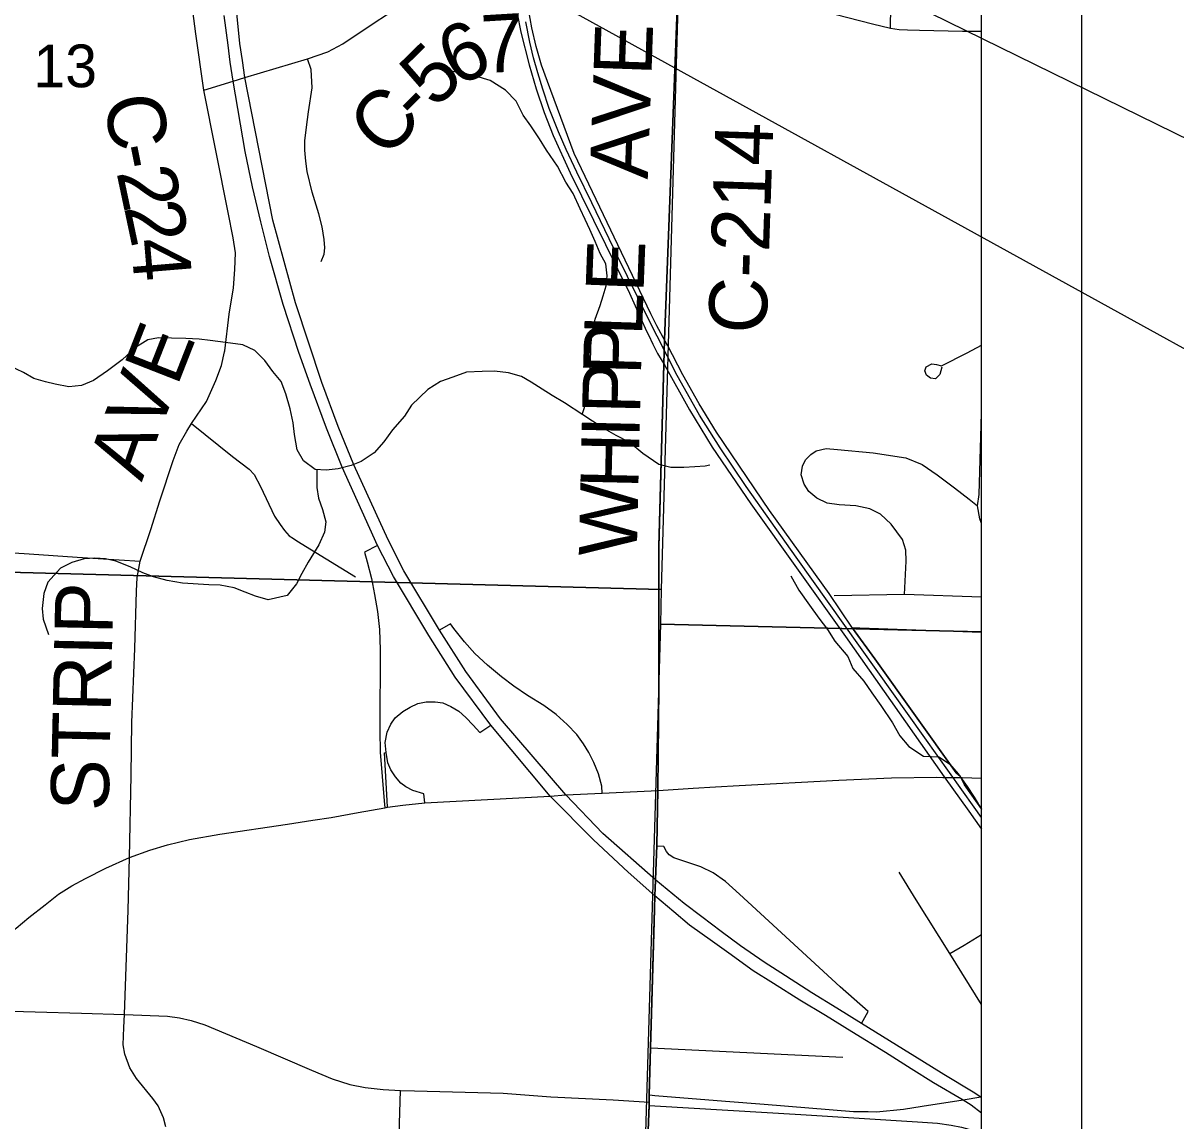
# Model space of a CAD drawing. Extents: x 0 to 34, y 0 to 22.
# Drawn here: x 8.698 to 9.827, y 17.297 to 18.372 of the extents above; entities that cross this region are included whole.
import ezdxf

# ---------------------------------------------------------------- set-up
doc = ezdxf.new("R2010")
doc.units = 0
for name, color, linetype in [('GM_X_City_Street', 7, 'Continuous'), ('GM_X_Corporation', 7, 'Continuous'), ('GM_X_County_Road', 7, 'Continuous'), ('GM_X_County_Road_Text', 7, 'Continuous'), ('GM_X_Interchange_Ramps', 7, 'Continuous'), ('GM_X_Interstate_Route', 7, 'Continuous'), ('GM_X_Minor_River', 7, 'Continuous'), ('GM_X_Rail_Line', 7, 'Continuous'), ('GM_X_Section_Text', 7, 'Continuous'), ('GM_X_Township_Road', 7, 'Continuous'), ('SH_Data', 7, 'Continuous'), ('SH_Text', 7, 'Continuous')]:
    doc.layers.add(name, color=color, linetype=linetype)

msp = doc.modelspace()

# ---------------------------------------------------------------- linework, layer by layer
at = {"layer": 'GM_X_City_Street'}
msp.add_line((9.6367, 17.9784), (9.637, 17.9905), dxfattribs=at)
for points in [[(9.5477, 18.3676), (9.5505, 18.5393), (9.5497, 18.5492), (9.5474, 18.5571), (9.5429, 18.5632)], [(9.598, 18.0352), (9.5961, 18.0281), (9.592, 18.0238), (9.5869, 18.0244), (9.5831, 18.0274), (9.5814, 18.0317), (9.5826, 18.0356), (9.5882, 18.0385), (9.593, 18.0378), (9.5979, 18.0366), (9.623, 18.0493), (9.637, 18.0569)]]:
    msp.add_lwpolyline(points, dxfattribs=at)
at = {"layer": 'GM_X_Corporation'}
for points in [[(7.1023, 20.9204), (2.837, 20.9204), (2.837, 14.1204), (9.637, 14.1204), (9.637, 20.9204), (9.4036, 20.9204), (9.4022, 20.8667), (9.2273, 20.8723), (9.1354, 20.8749), (9.124, 20.8753), (8.9858, 20.878), (8.9676, 20.8785), (8.8663, 20.881), (8.6259, 20.8892), (8.5535, 20.8914), (8.5421, 20.8915), (8.4667, 20.8934), (8.0602, 20.9055), (7.9522, 20.9084), (7.1104, 20.9188)], [(8.3333, 18.8624), (9.3514, 18.838), (9.3511, 18.8009), (9.3232, 17.8175), (8.3013, 17.8445)], [(9.637, 17.7759), (9.637, 18.7908), (9.3511, 18.8009), (9.3232, 17.8175), (9.3224, 17.7834)], [(8.3013, 17.8445), (9.3232, 17.8175), (9.3224, 17.7834), (9.2937, 16.8089), (8.2669, 16.8377)], [(9.637, 16.7685), (9.637, 17.7759), (9.3224, 17.7834), (9.2937, 16.8089), (9.2941, 16.7789)], [(9.637, 17.6026), (9.637, 17.7754), (9.5178, 17.7796), (9.5107, 17.7797), (9.5323, 17.7495), (9.612, 17.6378), (9.6161, 17.6346), (9.6203, 17.6261)]]:
    msp.add_lwpolyline(points, close=True, dxfattribs=at)
for points in [[(9.637, 14.7553), (9.637, 20.8621)], [(9.3401, 18.421), (9.3264, 18.0621), (9.3258, 18.0384), (9.321, 17.8596), (9.3207, 17.721), (9.32, 17.6211), (9.3188, 17.5666), (9.3177, 17.5332), (9.3173, 17.5248), (9.3168, 17.5178), (9.3167, 17.5046), (9.3128, 17.3688), (9.3114, 17.3225), (9.3115, 17.3158), (9.3114, 17.3124), (9.3077, 17.2197)], [(9.3077, 17.2197), (9.3114, 17.3124), (9.3115, 17.3158), (9.3114, 17.3225), (9.3128, 17.3688), (9.3167, 17.5046), (9.3168, 17.5178), (9.3173, 17.5248), (9.3177, 17.5332), (9.3188, 17.5666), (9.32, 17.6211), (9.3207, 17.721), (9.321, 17.8596), (9.3258, 18.0384), (9.3264, 18.0621), (9.3401, 18.421)], [(9.182, 18.3819), (9.1856, 18.3635), (9.1939, 18.3316), (9.2007, 18.3081), (9.2086, 18.285), (9.2174, 18.2622), (9.2341, 18.2258), (9.2452, 18.2031), (9.292, 18.1079), (9.3088, 18.0707), (9.3106, 18.0671), (9.3151, 18.0579), (9.3197, 18.0487), (9.3266, 18.0371), (9.3508, 17.9934), (9.373, 17.957), (9.4109, 17.9013), (9.5036, 17.7713), (9.6005, 17.634), (9.6246, 17.6002), (9.637, 17.5826), (9.637, 17.6026), (9.6203, 17.6261), (9.6161, 17.6346), (9.612, 17.6378), (9.5323, 17.7495), (9.5107, 17.7797), (9.4877, 17.8135), (9.4292, 17.8948), (9.3772, 17.9716), (9.3604, 17.9995), (9.3444, 18.0279), (9.3292, 18.0568), (9.3272, 18.0607), (9.3189, 18.0757), (9.313, 18.0876), (9.2378, 18.2446), (9.2117, 18.3152), (9.2058, 18.3313), (9.2007, 18.3494), (9.1965, 18.3677), (9.1931, 18.3862)]]:
    msp.add_lwpolyline(points, dxfattribs=at)
at = {"layer": 'GM_X_County_Road'}
for p, q in [((9.3202, 17.6205), (9.3206, 17.671)), ((9.593, 17.6335), (9.599, 17.6334)), ((9.599, 17.6334), (9.609, 17.6334)), ((9.6179, 17.6332), (9.637, 17.6326))]:
    msp.add_line(p, q, dxfattribs=at)
for points in [[(8.8752, 18.3068), (8.8672, 18.3619), (8.8625, 18.3998), (8.8597, 18.4111), (8.8534, 18.4289), (8.8412, 18.4603), (8.8205, 18.5154), (8.8175, 18.533), (8.8161, 18.548), (8.817, 18.5673), (8.8185, 18.588), (8.8196, 18.6158), (8.82, 18.6436), (8.8209, 18.7158)], [(9.3268, 18.0667), (9.3403, 18.4205), (9.3424, 18.5015), (9.3424, 18.5335), (9.3404, 18.5527), (9.336, 18.5745), (9.3314, 18.5903), (9.3271, 18.6029), (9.319, 18.6238)], [(8.8752, 18.3068), (8.9039, 18.3157), (8.9154, 18.3192), (8.9766, 18.3375), (8.9966, 18.3444), (9.0112, 18.3522), (9.0421, 18.3726), (9.0662, 18.3883), (9.0904, 18.4041), (9.1049, 18.4132), (9.1159, 18.4183), (9.1291, 18.4224), (9.1482, 18.425), (9.1708, 18.4247)], [(9.3403, 18.4205), (9.4334, 18.3962), (9.4817, 18.384), (9.5302, 18.3718), (9.5477, 18.3676), (9.5562, 18.3663), (9.5646, 18.3658), (9.5762, 18.3656), (9.6184, 18.3646), (9.637, 18.3645)], [(8.8957, 18.0514), (8.8999, 18.0871), (8.9042, 18.113), (8.9054, 18.1309), (8.906, 18.1475), (8.9039, 18.1619), (8.8988, 18.1867), (8.8752, 18.3068)], [(9.3262, 18.0461), (9.3266, 18.0616), (9.3268, 18.0667)], [(8.8126, 17.8453), (8.8233, 17.8761), (8.8321, 17.9045), (8.845, 17.944), (8.8511, 17.9597), (8.8585, 17.9726), (8.863, 17.98), (8.8776, 18.0017), (8.8868, 18.0223), (8.8925, 18.0368), (8.8955, 18.0503), (8.8957, 18.0514)], [(9.3212, 17.8539), (9.3212, 17.859), (9.326, 18.0379), (9.3262, 18.0461)], [(8.8023, 17.5549), (8.8038, 17.6353), (8.8047, 17.6873), (8.8075, 17.7597), (8.809, 17.8159), (8.8098, 17.8291), (8.8126, 17.8453)], [(9.3206, 17.671), (9.3209, 17.7204), (9.3212, 17.8539)], [(9.3994, 17.6253), (9.4973, 17.6307), (9.5487, 17.6329), (9.593, 17.6335)], [(9.609, 17.6334), (9.613, 17.6334), (9.6179, 17.6332)], [(9.0552, 17.6041), (9.0702, 17.6062), (9.0916, 17.6085), (9.2144, 17.6151), (9.2298, 17.6162), (9.2655, 17.618), (9.3202, 17.6205)], [(9.3162, 17.4807), (9.3169, 17.504), (9.317, 17.5172), (9.3175, 17.5243), (9.3179, 17.5327), (9.319, 17.5661), (9.3202, 17.6205)], [(9.3202, 17.6205), (9.3544, 17.6229), (9.3764, 17.6241), (9.3994, 17.6253)], [(8.982, 17.5913), (8.9999, 17.594), (9.0264, 17.5991), (9.0524, 17.6037), (9.0552, 17.6041)], [(8.8023, 17.5549), (8.8221, 17.5619), (8.8396, 17.5672), (8.861, 17.5725), (8.8908, 17.5777), (8.9572, 17.5875), (8.982, 17.5913)], [(8.6251, 17.4058), (8.6447, 17.4338), (8.66, 17.4535), (8.676, 17.4708), (8.6912, 17.4855), (8.7037, 17.4961), (8.7196, 17.5085), (8.7328, 17.5188), (8.7459, 17.5271), (8.7592, 17.5343), (8.7791, 17.5445), (8.8023, 17.5549)], [(8.8379, 17.2909), (8.8357, 17.2997), (8.8304, 17.3114), (8.825, 17.3189), (8.8092, 17.3384), (8.8026, 17.3489), (8.7976, 17.3622), (8.7961, 17.3712), (8.7966, 17.3883), (8.7974, 17.4011), (8.8011, 17.5032), (8.8023, 17.5549)], [(9.3084, 17.2321), (9.3116, 17.3118), (9.3117, 17.3152), (9.3116, 17.322), (9.313, 17.3683), (9.3162, 17.4807)], [(8.6251, 17.4058), (8.6641, 17.405), (8.7554, 17.4022), (8.7974, 17.4011), (8.8395, 17.3993), (8.8513, 17.3978), (8.8628, 17.3953), (8.8761, 17.391), (8.9267, 17.3697), (8.9807, 17.3464), (9.0008, 17.3379), (9.0183, 17.3326), (9.0333, 17.3294), (9.0509, 17.3276), (9.0678, 17.3266), (9.0816, 17.3261), (9.1682, 17.324), (9.215, 17.3205), (9.2762, 17.3173), (9.3117, 17.3152)]]:
    msp.add_lwpolyline(points, dxfattribs=at)
at = {"layer": 'GM_X_Interchange_Ramps'}
msp.add_line((9.4239, 17.3128), (9.3862, 17.3159), dxfattribs=at)
for points in [[(9.0453, 17.8606), (9.0324, 17.854), (9.0351, 17.8447), (9.0393, 17.8283), (9.0423, 17.8127), (9.0451, 17.7959), (9.0471, 17.7784), (9.0479, 17.7585), (9.0475, 17.682), (9.0475, 17.6789)], [(9.2655, 17.618), (9.2649, 17.6249), (9.2619, 17.637), (9.2571, 17.6479), (9.2524, 17.6576), (9.2469, 17.6663), (9.2404, 17.6754), (9.2312, 17.6852), (9.2202, 17.6951), (9.2081, 17.7037), (9.1921, 17.7136), (9.1788, 17.7228), (9.1666, 17.732), (9.1529, 17.7432), (9.1407, 17.7548), (9.1306, 17.7661), (9.1199, 17.7792), (9.1167, 17.7838), (9.106, 17.7777)], [(9.0916, 17.6085), (9.0905, 17.6172), (9.0798, 17.6204), (9.0729, 17.624), (9.068, 17.6278), (9.0629, 17.6338), (9.0582, 17.6407), (9.0555, 17.6477), (9.0538, 17.6576), (9.0529, 17.6677), (9.0547, 17.6777), (9.0584, 17.6856), (9.0625, 17.6916), (9.0701, 17.6979), (9.0774, 17.7021), (9.0848, 17.7057), (9.093, 17.7073), (9.1016, 17.7074), (9.1092, 17.7063), (9.1171, 17.7029), (9.1248, 17.6981), (9.1319, 17.6922), (9.139, 17.6846), (9.1456, 17.6772), (9.1564, 17.6845)], [(9.0475, 17.6789), (9.0478, 17.6582), (9.0517, 17.6104), (9.0524, 17.6037)], [(9.0552, 17.6041), (9.0546, 17.6107), (9.0521, 17.6575), (9.0538, 17.6576)], [(9.5195, 17.3921), (9.526, 17.4039), (9.4986, 17.4282), (9.3998, 17.5189), (9.3861, 17.5313), (9.374, 17.5399), (9.362, 17.5456), (9.3484, 17.5503), (9.3355, 17.5546), (9.331, 17.5574), (9.3284, 17.5607), (9.3259, 17.5655), (9.319, 17.5661)], [(9.3862, 17.3159), (9.3168, 17.3215), (9.3116, 17.322)], [(9.637, 17.3202), (9.6364, 17.32), (9.6189, 17.3172), (9.5789, 17.3109), (9.5606, 17.3081), (9.534, 17.3055), (9.5259, 17.3056)], [(9.3116, 17.3118), (9.317, 17.3117), (9.4601, 17.303)], [(9.5259, 17.3056), (9.5117, 17.3057), (9.4239, 17.3128)], [(9.4601, 17.303), (9.5742, 17.296), (9.5938, 17.2947), (9.6071, 17.2927), (9.6174, 17.2907), (9.628, 17.2876), (9.637, 17.2843)]]:
    msp.add_lwpolyline(points, dxfattribs=at)
at = {"layer": 'GM_X_Interstate_Route'}
for points in [[(9.106, 17.7777), (9.0712, 17.8356), (9.0558, 17.866), (9.022, 17.9397), (9.0067, 17.9772), (8.9908, 18.0203), (8.9648, 18.0983), (8.9426, 18.1794), (8.9154, 18.3192), (8.913, 18.3358), (8.9105, 18.3526), (8.9001, 18.4549), (8.894, 18.5339), (8.8855, 18.6428), (8.8804, 18.7046), (8.8705, 18.8229), (8.8664, 18.8766)], [(9.1564, 17.6845), (9.1213, 17.7317), (9.0956, 17.7723), (9.0608, 17.8302), (9.0453, 17.8606), (9.0105, 17.9373), (8.9952, 17.9756), (8.9792, 18.0187), (8.9681, 18.0498), (8.9528, 18.0967), (8.9395, 18.1437), (8.931, 18.1777), (8.9228, 18.212), (8.9156, 18.2467), (8.9039, 18.3157), (8.9009, 18.334), (8.8989, 18.3509), (8.895, 18.3799)], [(9.2298, 17.6162), (9.1656, 17.6907), (9.1317, 17.7371), (9.106, 17.7777)], [(9.637, 17.3044), (9.6267, 17.3121), (9.6189, 17.3172), (9.5899, 17.3342), (9.5682, 17.3479), (9.543, 17.3638), (9.5098, 17.3842), (9.4841, 17.4002), (9.4591, 17.4152), (9.4331, 17.4314), (9.4132, 17.4439), (9.3895, 17.461), (9.3734, 17.4727), (9.351, 17.4887), (9.3354, 17.5018), (9.317, 17.5172), (9.2908, 17.5404), (9.2569, 17.5723), (9.2144, 17.6151), (9.1564, 17.6845)], [(9.5195, 17.3921), (9.4953, 17.4071), (9.4709, 17.4224), (9.4448, 17.4388), (9.4241, 17.4523), (9.4007, 17.4684), (9.3818, 17.4824), (9.363, 17.4966), (9.3458, 17.5097), (9.3179, 17.5327), (9.2661, 17.5785), (9.2298, 17.6162)], [(9.637, 17.3196), (9.6364, 17.32), (9.6289, 17.3249), (9.5999, 17.3423), (9.5784, 17.3558), (9.5537, 17.3709), (9.5195, 17.3921)]]:
    msp.add_lwpolyline(points, dxfattribs=at)
at = {"layer": 'GM_X_Minor_River'}
for points in [[(9.2456, 17.989), (9.2506, 18.0038), (9.2519, 18.0164), (9.2529, 18.0266), (9.2539, 18.0377), (9.2544, 18.0563), (9.2554, 18.0685), (9.2586, 18.0822), (9.2634, 18.0956), (9.2663, 18.1051), (9.2692, 18.115), (9.2702, 18.1249), (9.2689, 18.1367), (9.2635, 18.1468), (9.2584, 18.1586), (9.2533, 18.1703), (9.2486, 18.1801), (9.2439, 18.1903), (9.2369, 18.2054), (9.2299, 18.2167), (9.2217, 18.2321), (9.2109, 18.2479), (9.2039, 18.2589), (9.1954, 18.2717), (9.188, 18.2822), (9.181, 18.2958), (9.1706, 18.3066), (9.1557, 18.3163), (9.1416, 18.3203), (9.1317, 18.3221), (9.1207, 18.3246), (9.1093, 18.3271), (9.0994, 18.3288)], [(9.3707, 17.9392), (9.3661, 17.9382), (9.3562, 17.9377), (9.3452, 17.9371), (9.3327, 17.9369), (9.3209, 17.9398), (9.3052, 17.9506), (9.2918, 17.9618), (9.2792, 17.9685), (9.2654, 17.9763), (9.2463, 17.9885), (9.2286, 18.0005), (9.2164, 18.0075), (9.2065, 18.0138), (9.1957, 18.0205), (9.1862, 18.0261), (9.1736, 18.0297), (9.1599, 18.0314), (9.1478, 18.0312), (9.1323, 18.0303), (9.119, 18.0255), (9.107, 18.0212), (9.0946, 18.0134), (9.0784, 17.998), (9.0718, 17.9872), (9.0598, 17.9738), (9.0516, 17.9623), (9.0419, 17.9515), (9.0291, 17.9429), (9.0193, 17.939), (9.0068, 17.9358), (8.9951, 17.9345), (8.9841, 17.9351), (8.9726, 17.9437), (8.9667, 17.9542), (8.9639, 17.9694), (8.9626, 17.9808), (8.9597, 17.9944), (8.9554, 18.0092), (8.951, 18.0213), (8.9426, 18.031), (8.9348, 18.0419), (8.9252, 18.0517), (8.9134, 18.0572), (8.8963, 18.0596), (8.8814, 18.0613), (8.8704, 18.0627), (8.8575, 18.0633), (8.8435, 18.0638), (8.8306, 18.064), (8.8204, 18.062), (8.8083, 18.0546), (8.7952, 18.0426), (8.7809, 18.0318), (8.767, 18.0221), (8.7553, 18.0174), (8.7428, 18.016), (8.7295, 18.0185), (8.72, 18.021), (8.7086, 18.0243), (8.6986, 18.0302), (8.6849, 18.0365)], [(8.9857, 17.935), (8.9858, 17.9173), (8.9875, 17.907), (8.9914, 17.8957), (8.9946, 17.8839), (8.9933, 17.8737), (8.9877, 17.8611), (8.9773, 17.8442), (8.971, 17.8331), (8.9659, 17.8231), (8.9569, 17.8116), (8.938, 17.8072), (8.9258, 17.8108), (8.9155, 17.8148), (8.9048, 17.8192), (8.8911, 17.8217), (8.8801, 17.8219), (8.8543, 17.8238), (8.8391, 17.8263), (8.8258, 17.8299), (8.8155, 17.8339), (8.8029, 17.8398), (8.7888, 17.8453), (8.7789, 17.8475), (8.7683, 17.8481), (8.758, 17.8476), (8.7459, 17.844), (8.7346, 17.8385), (8.7223, 17.8246), (8.7183, 17.8136), (8.7169, 17.7987), (8.7178, 17.7885), (8.723, 17.7734)], [(9.4502, 17.8307), (9.458, 17.8167), (9.4684, 17.8021), (9.4777, 17.7893), (9.4862, 17.7784), (9.4932, 17.7667), (9.5059, 17.7517), (9.511, 17.74), (9.5218, 17.7276), (9.5295, 17.7163), (9.5384, 17.7039), (9.5497, 17.6869), (9.557, 17.6741), (9.5659, 17.6636), (9.5801, 17.6543), (9.5953, 17.6534), (9.6056, 17.6467), (9.6141, 17.6369), (9.623, 17.6245), (9.6299, 17.614), (9.637, 17.602)]]:
    msp.add_lwpolyline(points, dxfattribs=at)
at = {"layer": 'GM_X_Rail_Line'}
msp.add_lwpolyline([(9.637, 17.5941), (9.6299, 17.6042), (9.5815, 17.6722), (9.4554, 17.8491), (9.4063, 17.9185), (9.381, 17.9563), (9.3608, 17.9884), (9.3388, 18.027), (9.3093, 18.0849), (9.2808, 18.1433), (9.2553, 18.1964), (9.2404, 18.2264), (9.23, 18.2485), (9.2226, 18.2658), (9.2133, 18.2889), (9.2071, 18.3078), (9.2024, 18.3236), (9.1981, 18.3384), (9.1945, 18.3539), (9.1905, 18.3737)], dxfattribs=at)
at = {"layer": 'GM_X_Township_Road'}
for p, q in [((8.7511, 17.8492), (8.8126, 17.8453)), ((9.313, 17.3683), (9.5012, 17.3592))]:
    msp.add_line(p, q, dxfattribs=at)
for points in [[(8.9902, 18.1388), (8.9931, 18.146), (8.9936, 18.1524), (8.993, 18.1604), (8.9912, 18.1727), (8.9878, 18.1854), (8.9813, 18.2069), (8.9764, 18.227), (8.9749, 18.237), (8.9739, 18.2479), (8.9742, 18.2571), (8.9756, 18.2706), (8.9777, 18.2854), (8.9811, 18.309), (8.9802, 18.3269), (8.9766, 18.3375)], [(8.863, 17.98), (8.9032, 17.9478), (8.9195, 17.9353), (8.9244, 17.9301), (8.9305, 17.9185), (8.9445, 17.8894), (8.9499, 17.8812), (8.9543, 17.8752), (8.9588, 17.8702), (8.963, 17.8673)], [(9.637, 17.8821), (9.6352, 17.8868), (9.6329, 17.8993), (9.6346, 17.9105), (9.6367, 17.9784)], [(9.5615, 17.8126), (9.5631, 17.8451), (9.5627, 17.8561), (9.5596, 17.8666), (9.5486, 17.8815), (9.538, 17.8913), (9.5275, 17.8966), (9.5137, 17.8996), (9.4974, 17.9004), (9.4857, 17.9021), (9.4756, 17.907), (9.4679, 17.9135), (9.4633, 17.9206), (9.4604, 17.9299), (9.4617, 17.9383), (9.4646, 17.9445), (9.4696, 17.9498), (9.4751, 17.9534), (9.4849, 17.9555), (9.4958, 17.9548), (9.5308, 17.9515), (9.5627, 17.9465), (9.5787, 17.9401), (9.5934, 17.9298), (9.6104, 17.9172), (9.6249, 17.9059), (9.6329, 17.8993)], [(8.963, 17.8673), (8.9663, 17.8651), (9.0238, 17.83)], [(8.3723, 17.8619), (8.3982, 17.86), (8.4658, 17.8568), (8.5196, 17.8561), (8.5572, 17.8568), (8.5697, 17.8571), (8.6121, 17.8571), (8.6431, 17.8561), (8.6738, 17.8543), (8.7039, 17.8523), (8.7511, 17.8492)], [(9.637, 17.81), (9.5615, 17.8126), (9.4925, 17.8114)], [(9.637, 17.4107), (9.6058, 17.4607), (9.5728, 17.5134), (9.5564, 17.5406)], [(9.6058, 17.4607), (9.6201, 17.469), (9.637, 17.4795)], [(9.0562, 16.9918), (9.0592, 17.0456), (9.0678, 17.3266)]]:
    msp.add_lwpolyline(points, dxfattribs=at)
at = {"layer": 'SH_Data'}
msp.add_line((9.7349, 21.0001), (9.7349, 14.0001), dxfattribs=at)
at = {"layer": 'SH_Text'}
msp.add_lwpolyline([(10.6613, 17.855), (6.4321, 19.9298), (10.6613, 17.5984)], close=True, dxfattribs=at)

# ---------------------------------------------------------------- texts
at = {"layer": 'GM_X_County_Road_Text'}
for s, height, rotation, p in [('6', 0.0568, 26.1485, (9.1228, 18.3093)), ('7', 0.0568, 3.4523, (9.1485, 18.3232)), ('AVE', 0.05682, 87.9903, (9.31, 18.2191)), ('5', 0.0568, 44.3854, (9.1017, 18.2876)), ('C', 0.0568, 45.2815, (9.0525, 18.238)), ('C', 0.0568, 278.8245, (8.7771, 18.2989)), ('-', 0.0568, 45.1435, (9.0854, 18.2712)), ('C-214', 0.05682, 88.0725, (9.4261, 18.0675)), ('-', 0.0568, 281.2576, (8.7847, 18.2502)), ('2', 0.0568, 281.94, (8.7894, 18.2265)), ('2', 0.0568, 281.9305, (8.7967, 18.1923)), ('4', 0.0568, 274.793, (8.8036, 18.1599)), ('E', 0.0568, 87.831, (9.3058, 18.1078)), ('L', 0.0568, 88.0669, (9.3044, 18.0654)), ('E', 0.0568, 68.6108, (8.8489, 18.0156)), ('P', 0.0568, 88.4271, (9.3033, 18.0271)), ('V', 0.0568, 68.76, (8.8308, 17.969)), ('P', 0.0568, 88.6599, (9.3024, 17.9889)), ('I', 0.0568, 88.6838, (9.3019, 17.9656)), ('A', 0.0568, 70.5789, (8.8143, 17.9223)), ('H', 0.0568, 88.6822, (9.3007, 17.9156)), ('W', 0.0568, 88.6802, (9.2992, 17.8497)), ('STRIP', 0.05682, 88.7379, (8.7817, 17.6))]:
    msp.add_text(s, height=height, rotation=rotation, dxfattribs=at).set_placement(p)
at = {"layer": 'GM_X_Section_Text'}
msp.add_text('13', height=0.04186, rotation=0, dxfattribs=at).set_placement((8.7082, 18.3096))

doc.saveas('drawing.dxf')
